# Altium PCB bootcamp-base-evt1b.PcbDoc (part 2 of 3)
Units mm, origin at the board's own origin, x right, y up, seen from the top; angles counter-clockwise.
Board outline 49.31 x 77.41 mm, 4 copper layers (Top Layer, Internal Plane 1, Internal Plane 2, Bottom Layer), stack 1.597 mm thick; 178 components, 122 nets, 1398 pads, 353 vias.
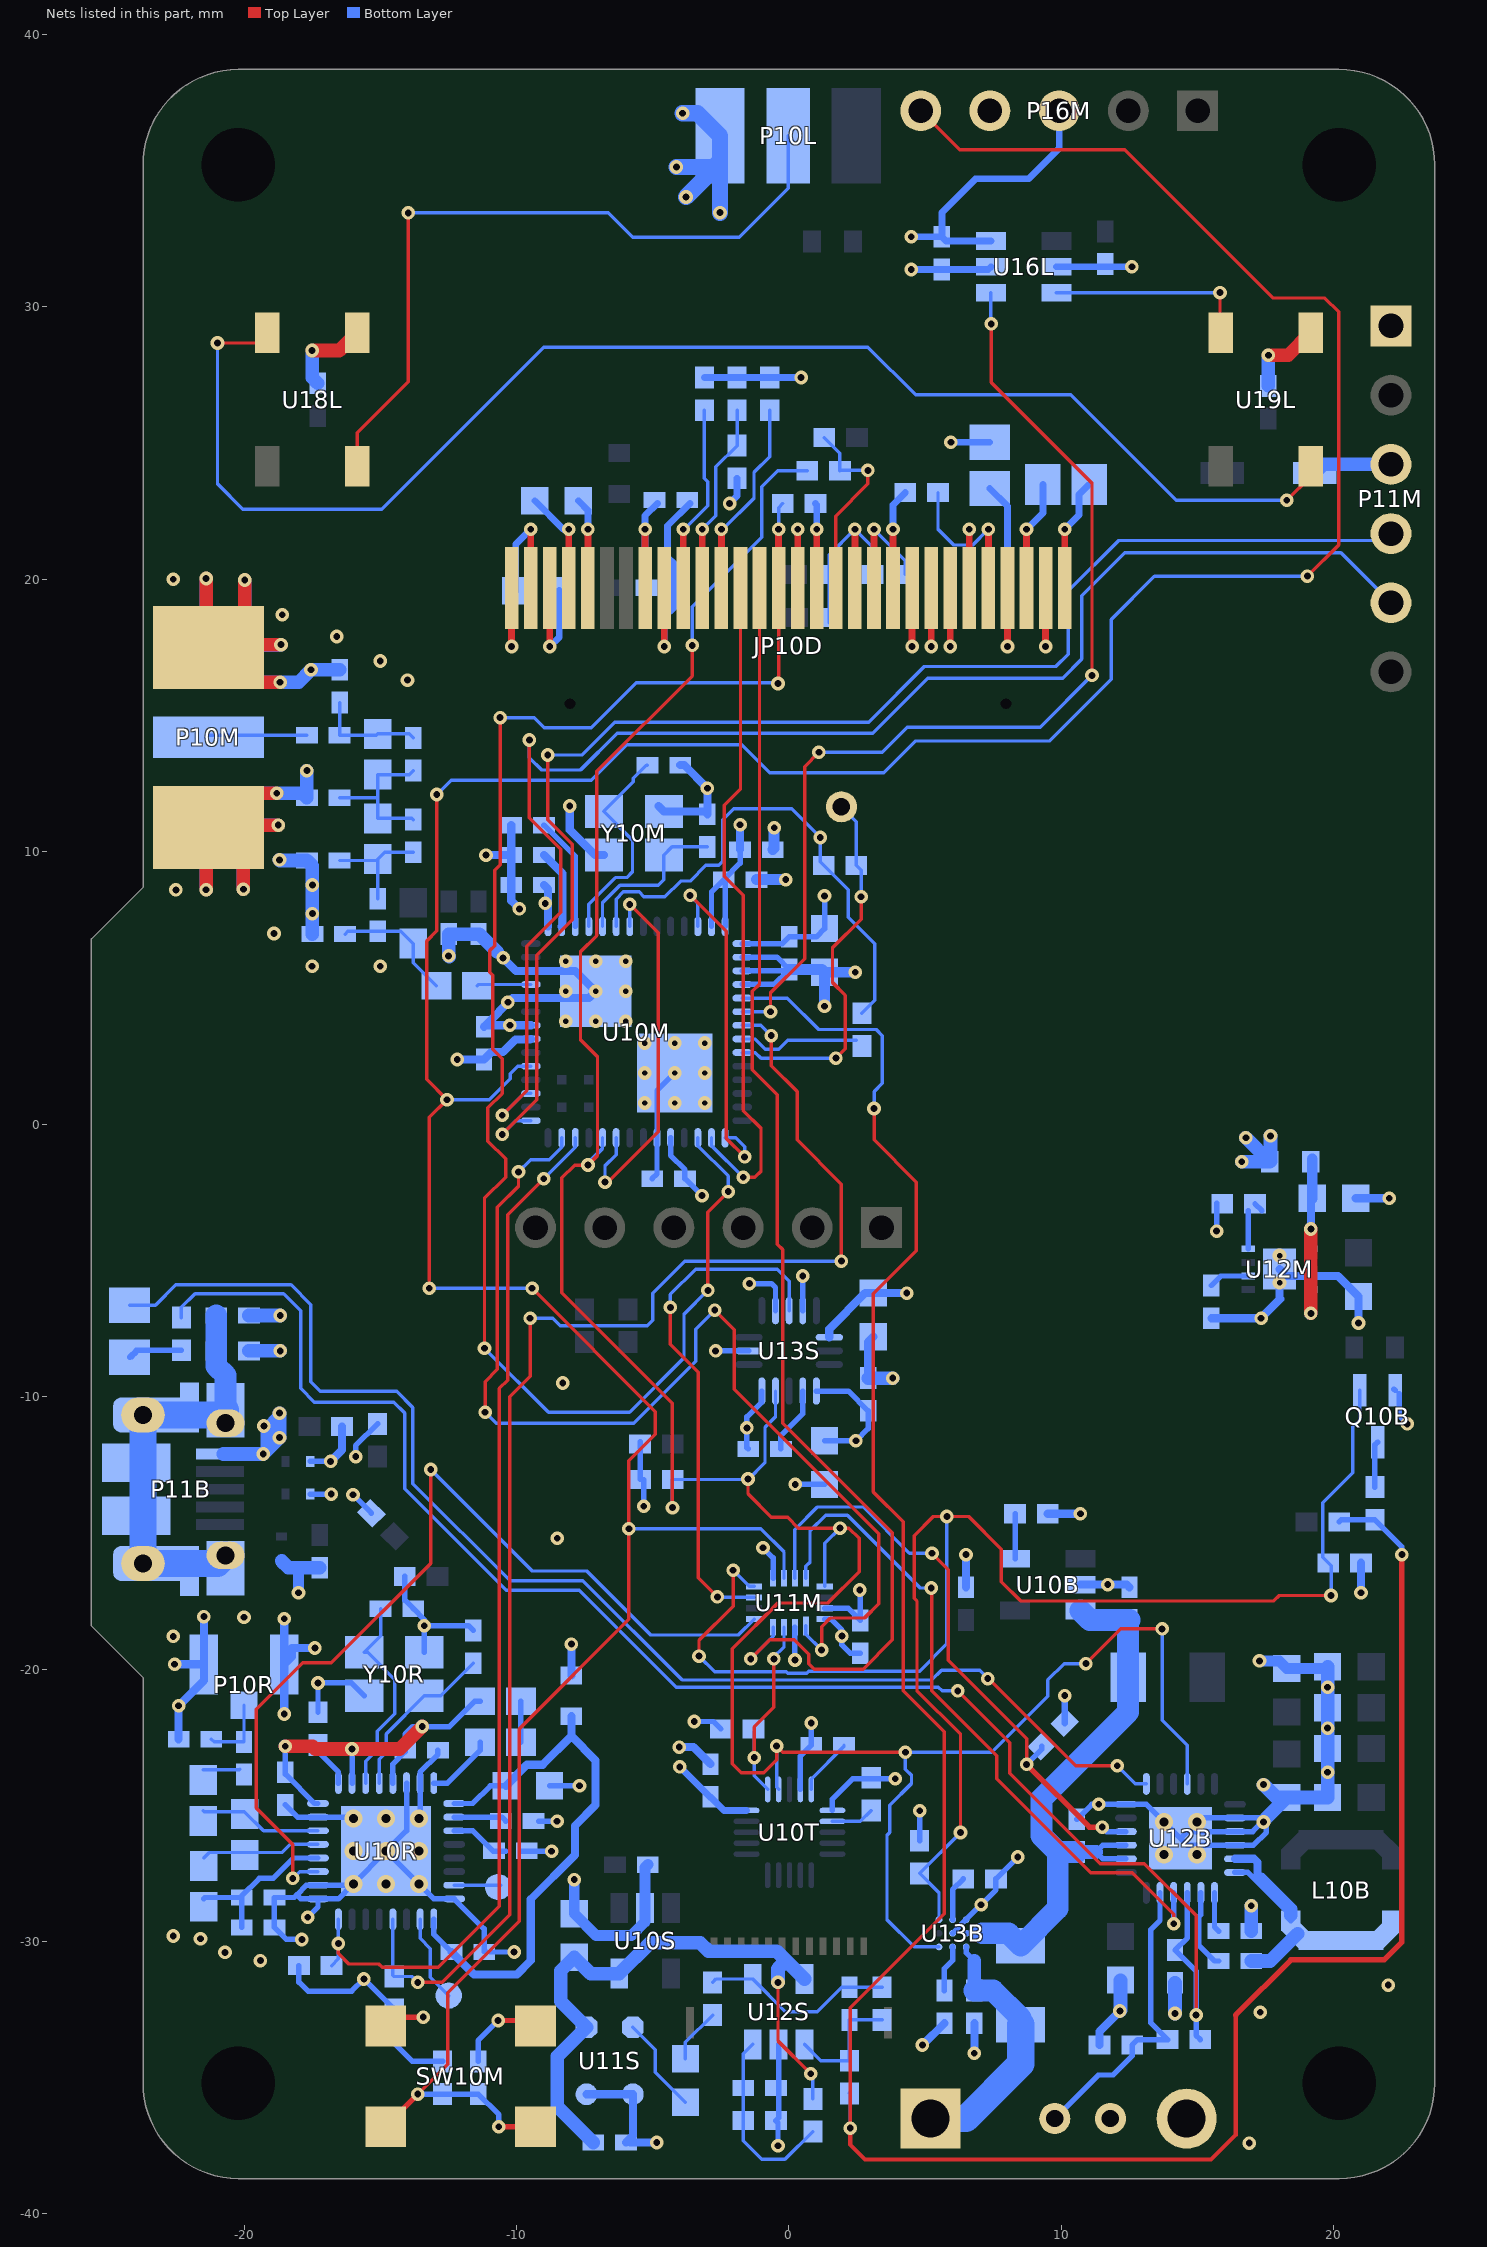
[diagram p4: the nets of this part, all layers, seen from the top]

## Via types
v1: diameter 0.5, hole 0.25, Top Layer to Bottom Layer, tented both sides, 320 vias
v2: diameter 0.5, hole 0.2, Top Layer to Bottom Layer, 18 vias
v3: diameter 0.66, hole 0.33, Top Layer to Bottom Layer, tented top, 13 vias
v4: diameter 0.5, hole 0.2, Top Layer to Bottom Layer, tented top, 2 vias

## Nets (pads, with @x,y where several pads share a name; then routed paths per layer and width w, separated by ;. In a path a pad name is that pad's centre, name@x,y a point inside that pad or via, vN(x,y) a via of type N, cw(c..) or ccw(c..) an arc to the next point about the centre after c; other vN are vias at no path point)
ACCEL_INT: U11M.7 U13S.11 | length 19.2
  Top Layer w0.125: v1(-4.35,-6.725) -4.35,-8.075 -3.325,-9.1 -3.325,-16.65 v1(-2.625,-17.35)
  Bottom Layer w0.125: v1(-4.35,-6.725) -4.35,-6.25 -3.425,-5.325 -0.425,-5.325 0.008,-5.758 U13S.11@0.008,-6.846 ; v1(-2.625,-17.35) -2.608,-17.367 U11M.7@-1.279,-17.367
BAT_CD: U11M.12 U12B.4 | length 25.6
  Top Layer w0.125: v1@5.25,-17.025 5.25,-20.8 7.625,-23.175 7.625,-24.025 11.075,-27.475 12.6,-27.475 14.125,-29 v1(14.125,-29.35)
  Bottom Layer w0.125: U11M.12@0.621,-16.667 0.621,-16.229 0.775,-16.075 0.775,-14.925 1.35,-14.35 2.15,-14.35 4.825,-17.025 v1(5.225,-17.025)
  Bottom Layer w0.2: U12B.4@14.122,-28.216 14.122,-29.347 v1(14.125,-29.35)
BAT_DRV: C23B.1 R17B.1 R18B.2 U12B.3 | length 60.8
  Top Layer w0.125: v1(6.2,-20.8) 8.1,-22.7 8.1,-23.825 11.425,-27.15 13.05,-27.15 14.947,-29.047 v1(14.947,-32.7)
  Bottom Layer w0.125: R17B.1@-22.3,-7.1 -22.3,-6.725 -21.8,-6.225 -18.55,-6.225 -17.925,-6.85 -17.925,-9.7 -17.425,-10.2 -14.5,-10.2 -14.1,-10.6 -14.1,-13.375 -10.375,-17.1 -7.7,-17.1 -4.139,-20.661 5.486,-20.661 5.625,-20.8 v1(6.2,-20.8)
  Bottom Layer w0.2: U12B.3@14.622,-28.216 14.622,-29.866 C23B.1@14.172,-30.316 14.947,-31.091 v1(14.947,-32.7) 14.947,-33.447 R18B.2@15.1,-33.6
BAT_INT: R19B.1 U11M.11 U12B.10 | length 22.6
  Top Layer w0.125: v1(5.25,-15.75) 5.85,-16.35 5.85,-19.675 8.725,-22.55 v1(8.725,-23.5)
  Top Layer w0.2: v1(8.725,-23.5) 11.025,-25.8 v1(11.5,-25.8)
  Bottom Layer w0.125: U11M.11@0.221,-16.667 0.221,-14.879 1.05,-14.05 2.725,-14.05 4.425,-15.75 v1(5.25,-15.75)
  Bottom Layer w0.2: v1(8.725,-23.5) 9.276,-22.949 R19B.1@9.276,-22.824 ; v1(11.5,-25.8) 11.666,-25.966 U12B.10@12.372,-25.966
BAT_PMID: C22B.1 U12B.1 | length 1.5
  Bottom Layer w0.2: U12B.1@15.622,-28.216 15.622,-29.466 C22B.1@15.772,-29.616
BAT_POS: C10B.1 C21B.1 R21B.1 R25B.1 U10B.3 U12B.8 U12B.9 U13B.C2 | length 22
  Bottom Layer w0.2: U13B.C2@6.508,-29.7 6.9,-29.7 ; U12B.8@12.372,-26.966 11.522,-26.966 11.272,-26.716 11.522,-26.466 U12B.9@12.372,-26.466
  Bottom Layer w0.4: 6.9,-29.7 7.1,-29.7
  Bottom Layer w0.5: C21B.1@10.572,-26.716 11.272,-26.716
  Bottom Layer w0.8: 7.1,-29.7 8.058,-29.7 R21B.1@8.508,-30.15 9.872,-28.787 9.872,-26.716 ; C21B.1@10.572,-26.716 9.872,-26.716 ; U10B.3@10.7,-17.85 11.05,-18.2 C10B.1@12.5,-18.2 12.45,-18.25 R25B.1@12.45,-20.3 12.45,-21.575 9.272,-24.753 9.272,-26.116 9.872,-26.716
BAT_RAW: C25B.1 J10B.1 R21B.2 U13B.C3 | length 9.7
  Bottom Layer w0.2: U13B.C3@6.508,-30.2 6.508,-30.408 6.8,-30.7
  Bottom Layer w0.5: 6.8,-30.7 6.808,-30.708 C25B.1@6.808,-31.8
  Bottom Layer w0.8: C25B.1@6.808,-31.8 7.5,-31.8 8.508,-32.808 R21B.2@8.508,-33.05
  Bottom Layer w1: J10B.1@5.2,-36.5 6.5,-36.5 8.508,-34.492 R21B.2@8.508,-33.05
BAT_STAT: D10B.2 U12B.13 | length 48.7
  Top Layer w0.125: v1@7.35,-20.375 10.525,-23.55 v1(12.05,-23.55)
  Bottom Layer w0.125: D10B.2@-24.2,-6.65 -23.25,-6.65 -22.5,-5.9 -18.275,-5.9 -17.55,-6.625 -17.55,-9.45 -17.2,-9.8 -14.4,-9.8 -13.8,-10.4 -13.8,-13.2 -10.236,-16.764 -7.561,-16.764 -3.925,-20.4 5.25,-20.4 5.6,-20.05 7,-20.05 v1(7.3,-20.35) ; v1(12.05,-23.55) 12.716,-24.216 U12B.13@13.122,-24.216
BAT_SW: C14B.2 L10B.1 U12B.23 U12B.24 | length 8.3
  Bottom Layer w0.2: U12B.24@16.372,-27.466 16.847,-27.466 18.422,-29.041 L10B.1@18.422,-29.241
  Bottom Layer w0.3: U12B.23@16.372,-26.966 17.072,-26.966 17.197,-27.091 17.197,-27.716
  Bottom Layer w0.5: C14B.2@16.972,-30.716 17.672,-30.716 L10B.1@18.672,-29.716 ; 17.322,-27.716 18.422,-28.816 L10B.1@18.422,-29.041
BAT_TS: J11B.1 R18B.1 R20B.2 U12B.5 | length 11.4
  Bottom Layer w0.2: J11B.1@9.76,-36.5 11.36,-34.9 11.9,-34.9 12.6,-34.2 R20B.2@12.6,-33.8 12.8,-33.6 R18B.1@13.9,-33.6 13.275,-32.975 13.275,-29.575 13.622,-29.228 U12B.5@13.622,-28.216
BLE_ANT: C14R.2 C15R.2 P10R.SIG | length 2.6
  Bottom Layer w0.125: C15R.2@-21.2,-22.575 -21.1,-22.675 C14R.2@-20,-22.675 P10R.SIG@-20,-21.325
BLE_ANT1: L13R.2 L14R.1 U10R.21 | length 4.4
  Bottom Layer w0.125: L14R.1@-21.486,-26.934 -21.286,-26.734 -19.986,-26.734 -18.611,-26.734 -18.311,-26.434 U10R.21@-17.286,-26.434
BLE_ANT2: L12R.1 L13R.1 U10R.22 | length 4.5
  Bottom Layer w0.125: L12R.1@-21.5,-25.2 -21.466,-25.234 -19.986,-25.234 -19.286,-25.934 U10R.22@-17.286,-25.934
BLE_AVDD: C12R.1 C13R.1 L10R.2 U10R.24 U10R.26 U10R.29 | length 14.6
  Top Layer w0.5: v1(-18.486,-22.834) -17.486,-22.834 -17.386,-22.934 v1(-16.036,-22.934) -14.286,-22.934 v1(-13.461,-22.109)
  Bottom Layer w0.2: v1(-18.486,-22.834) C13R.1@-18.486,-23.784 -18.486,-23.859 -17.411,-24.934 U10R.24@-17.286,-24.934 ; U10R.26@-16.036,-24.184 v1(-16.036,-22.934) ; U10R.29@-14.536,-24.184 -14.536,-23.484 -14.086,-23.034 C12R.1@-14.086,-22.984 -14.086,-22.384 -13.811,-22.109 v1(-13.461,-22.109) -12.461,-22.109 -11.536,-21.184 L10R.2@-11.336,-21.184
BLE_IREF: R10R.2 U10R.25 | length 1.7
  Bottom Layer w0.2: R10R.2@-17.286,-22.784 -17.286,-23.034 -16.536,-23.784 U10R.25@-16.536,-24.184
BLE_RDYN: R11R.1 U10M.26 U10R.16 | length 38.6
  Top Layer w0.125: v1(-16.536,-30.075) -16.536,-30.439 -16.15,-30.825 -15.05,-30.825 -14.925,-30.95 -12.875,-30.95 -10.625,-28.7 -10.625,-9.7 -10.325,-9.4 -10.325,-3.325 v1(-9,-2)
  Bottom Layer w0.125: R11R.1@-16.786,-30.884 -16.536,-30.634 v1(-16.536,-30.075) U10R.16@-16.536,-29.184 ; v1(-9,-2) -7.842,-0.842 U10M.26@-7.842,-0.501
BLE_REQN: R12R.1 U10M.7 U10R.12 | length 53.4
  Top Layer w0.125: v1(-13.625,-31.5) -12.725,-31.5 -10.25,-29.025 -10.25,-10 -9.5,-9.25 v1(-9.5,-7.125) ; v1(-0.65,3.25) -0.65,2.15 0.3,1.2 0.3,-0.575 1.925,-2.2 v1(1.925,-5.025)
  Bottom Layer w0.125: U10R.12@-14.536,-29.184 -14.536,-31.234 R12R.1@-14.486,-31.284 -13.841,-31.284 v1(-13.625,-31.5) ; v1(-9.5,-7.125) -8.675,-7.125 -8.4,-7.4 -5.2,-7.4 -5,-7.2 -5,-6.2 -3.825,-5.025 v1(1.925,-5.025) ; U10M.7@-1.712,3.629 -1.029,3.629 v1(-0.65,3.25)
BLE_RST: U10R.19 U11M.5 | length 34.5
  Top Layer w0.125: v1(-18.211,-27.684) -18.211,-26.439 -19.55,-25.1 -19.55,-21.475 -17.85,-19.775 -16.8,-19.775 -13.15,-16.125 v1(-13.15,-12.675)
  Bottom Layer w0.125: v1(-18.211,-27.684) -17.961,-27.434 U10R.19@-17.286,-27.434 ; v1(-13.15,-12.675) -9.425,-16.4 -7.425,-16.4 -5.075,-18.75 -1.862,-18.75 U11M.5@-1.279,-18.167
BLE_VDDPA: C19R.2 C20R.2 L14R.2 U10R.20 | length 6
  Bottom Layer w0.2: L14R.2@-21.486,-28.434 -21.436,-28.384 C19R.2@-20.086,-28.384 ; C20R.2@-20.086,-29.484 C19R.2@-20.086,-28.384 ; U10R.20@-17.286,-26.934 -18.186,-26.934 -18.936,-27.684 -19.436,-27.684 -20.086,-28.334 C19R.2@-20.086,-28.384
BLE_XC1: C10R.1 U10R.28 Y10R.2 | length 6.2
  Bottom Layer w0.125: U10R.28@-15.036,-24.184 -15.036,-23.309 -14.786,-23.059 -14.786,-22.384 Y10R.2@-13.386,-20.984 -12.786,-20.984 C10R.1@-11.586,-19.784
BLE_XC2: C11R.1 U10R.27 Y10R.1 | length 7.6
  Bottom Layer w0.125: U10R.27@-15.536,-24.184 -15.536,-23.384 -15.111,-22.959 -15.111,-22.284 -14.461,-21.634 -14.461,-20.384 -15.461,-19.384 Y10R.1@-15.586,-19.384 -14.986,-18.784 C11R.1@-14.986,-17.784
BS0: JP10D.10 R11D.2 | length 7
  Top Layer w0.25: JP10D.10@-3.878,19.684 v1(-3.878,21.834)
  Bottom Layer w0.125: v1(-3.878,21.834) -3.838,21.834 -2.978,22.694 -2.978,23.584 -3.103,23.709 R11D.2@-3.103,26.209
BS1: JP10D.11 R15D.2 R16D.2 | length 7.1
  Top Layer w0.25: JP10D.11@-3.178,19.684 v1(-3.178,21.834)
  Bottom Layer w0.125: v1(-3.178,21.834) -2.678,22.334 -2.678,24.134 R16D.2@-1.903,24.909 R15D.2@-1.903,26.209
BS2: JP10D.12 R17D.2 | length 7.3
  Top Layer w0.25: JP10D.12@-2.478,19.684 v1(-2.478,21.834)
  Bottom Layer w0.125: v1(-2.478,21.834) -2.428,21.834 -1.281,22.981 -1.281,23.922 -0.703,24.5 R17D.2@-0.703,26.209
DAC0_OUT: J17M.1 R15M.2 U10M.9 | length 13.8
  Top Layer w0.125: v1(1.725,2.425) 2.075,2.775 2.075,4.725 1.6,5.2 1.6,6.475 2.65,7.525 v1(2.65,8.35)
  Bottom Layer w0.125: U10M.9@-1.712,2.629 -1.229,2.629 -1.025,2.425 v1(1.725,2.425) ; J17M.1@1.925,11.65 2.475,11.1 R15M.2@2.475,9.5 2.65,9.325 v1(2.65,8.35) v1@2.675,8.35
DUART_RX: P11M.4 U10M.29 | length 52.3
  Top Layer w0.125: v1(-10.525,-0.375) -9.25,0.9 -9.25,6.2 -7.95,7.5 -7.95,10.275 -8.85,11.175 v1(-8.85,13.55)
  Bottom Layer w0.125: v1(-10.525,-0.375) -10.021,0.129 U10M.29@-9.472,0.129 ; v1(-8.85,13.55) -7.6,13.55 -6.4,14.75 2.925,14.75 4.975,16.8 9.8,16.8 10.25,17.25 10.25,19.575 12.1,21.425 21.825,21.425 22.08,21.68 P11M.4@22.1,21.68
DUART_TX: P11M.5 U10M.31 | length 54.4
  Top Layer w0.125: v1(-10.525,0.325) -9.625,1.225 -9.625,6.525 -8.375,7.775 -8.375,10.099 -9.525,11.249 v1(-9.525,14.1)
  Bottom Layer w0.125: v1(-10.525,0.325) -9.721,1.129 U10M.31@-9.472,1.129 ; v1(-9.525,14.1) -9.525,13.45 -9.075,13 -7.65,13 -6.3,14.35 3.075,14.35 5.1,16.375 10.05,16.375 10.75,17.075 10.75,19.4 12.325,20.975 20.265,20.975 P11M.5@22.1,19.14
GG_INT: Q10B.1 R22B.1 R28B.2 U11M.8 U13B.A1 | length 60.8
  Top Layer w0.125: v1(-3.3,-19.525) -3.3,-18.95 -2.05,-17.7 v1(-2.05,-16.375) ; v1(6.3,-26) 6.3,-22.4 4.7,-20.8 4.7,-17.5 4.6,-17.4 4.6,-15.1 5.3,-14.4 v1(5.8,-14.4) 6.6,-14.4 7.8,-15.6 7.8,-16.8 8.5,-17.5 17.8,-17.5 18,-17.3 v1(19.9,-17.3)
  Bottom Layer w0.125: v1(-3.3,-19.525) -2.725,-20.1 -0.1,-20.1 -0.05,-20.15 0.65,-20.15 0.725,-20.075 4.8,-20.075 5.8,-19.075 v1(5.8,-14.4) ; v1(-2.05,-16.375) -1.458,-16.967 U11M.8@-1.279,-16.967 ; U13B.A1@5.508,-29.2 5.508,-28.208 R22B.1@4.8,-27.5 v1(6.3,-26) ; v1(19.9,-17.3) 19.9,-16.2 R28B.2@19.8,-16.1 19.6,-15.9 19.6,-13.9 20.7,-12.8 20.7,-11.1 20.958,-10.842 Q10B.1@20.958,-9.771
GG_VDD: C26B.1 U13B.B3 | length 1.7
  Bottom Layer w0.2: C26B.1@5.708,-31.8 5.708,-30.992 6.008,-30.692 U13B.B3@6.008,-30.2
GND: C10B.2 C10L.2 C10M.2 C10R.2 C10S.2 C10T.2 C11B.2 C11L.2 C11M.2 C11R.2 C11S.2 C11T.2 C12D.2 C12L.2 C12M.2 C12R.2 C13D.2 C13L.2 C13M.2 C13R.2 C14D.2 C14M.2 C14S.2 C15B.2 C15D.2 C15M.2 C15R.1 C15S.2 C16B.2 C16M.2 C16R.2 C16S.2 C17B.2 C17M.2 C17R.2 C17S.2 C18B.2 C18M.2 C18R.1 C18S.2 C19B.2 C19M.2 C19R.1 C19S.2 C20B.2 C20M.2 C20R.1 C21B.2 C21R.2 C22B.2 C23B.2 C24B.2 C25B.2 C25M.2 C26B.2 C26M.1 C27B.2 C27M.2 C28B.2 C28M.2 C29M.2 C30M.2 C31M.2 C32M.2 C33M.2 C34M.2 C35M.1 D11B.2 D12B.2 D13B.2 J12B.1 J13B.1 JP10D.1 JP10D.8 JP10D.16 JP10D.17 JP10D.21 JP10D.22 JP10D.23 JP10D.24 JP10D.25 JP10D.29 JP10D.30 P10L.1 P10M.2 P10R.GND P11B.5 P11M.1 P16M.4 Q10B.2 R10R.1 R11D.1 R13S.1 R14D.2 R15D.1 R16B.2 R17D.1 R18D.2 R20B.1 R23B.1 R24B.2 R28B.1 R31B.2 R32B.2 R34T.1 SW10M.1 SW10M.2 U10B.2 U10M.2 U10M.3 U10M.4 U10M.20 U10M.36 U10M.38 U10M.40 U10M.61 U10M.62 U10R.8 U10R.17 U10R.18 U10R.23 U10R.30 U10R.31 U10R.33 U10S.2 U10T.4 U10T.6 U11M.9 U11M.16 U11S.2 U11S.3 U12B.12 U12B.20 U12B.21 U12B.22 U12B.25 U12M.3 U12M.9 U12S.2 U13B.B2 U13B.C1 U13S.5 U13S.7 U13S.10 U13S.12 U16L.2 U16L.5 U18L.3 U19L.3 Y10M.3 Y10M.4 Y10R.3 Y10R.4 | length 300.3
  Top Layer w0.2: SW10M.2@-14.8,-33.1 -14.475,-32.775 v1(-13.425,-32.775) ; v1(-10.675,-32.9) -9.5,-32.9 SW10M.1@-9.3,-33.1
  Top Layer w0.25: v1(-10.178,17.534) JP10D.1@-10.178,19.684 ; JP10D.8@-5.278,19.684 v1(-5.278,21.834) ; JP10D.16@0.322,19.684 v1(0.322,21.834) ; JP10D.17@1.022,19.684 v1(1.022,21.834) ; JP10D.21@3.822,19.684 v1(3.822,21.834) ; v1(4.522,17.534) JP10D.22@4.522,19.684 ; v1(5.222,17.534) JP10D.23@5.222,19.684 ; v1(5.922,17.534) JP10D.24@5.922,19.684 ; JP10D.25@6.622,19.684 v1(6.622,21.834) ; v1(9.422,17.534) JP10D.29@9.422,19.684 ; JP10D.30@10.122,19.684 v1(10.122,21.834)
  Top Layer w0.5: v1(-21.392,8.604) -21.392,10.814 P10M.2@-21.307,10.898 ; v1(-21.392,20.029) -21.392,17.586 P10M.2@-21.307,17.502 ; v1(-20.025,8.625) -20.025,9.616 P10M.2@-21.307,10.898 ; v1(-19.975,19.975) -19.975,18.834 P10M.2@-21.205,17.604 ; v1(-18.8,12.15) -20.055,12.15 P10M.2@-21.226,10.979 ; v1(-18.742,10.979) P10M.2@-21.226,10.979 ; v1(-18.675,16.225) -20.03,16.225 P10M.2@-21.307,17.502 ; v1(-18.642,17.604) P10M.2@-21.205,17.604 ; v1(-17.5,28.4) -16.5,28.4 U18L.3@-15.85,29.05 ; v1(17.6,28.225) 18.325,28.225 U19L.3@19.15,29.05 ; P10M.2@-21.307,10.898 P10M.2@-21.226,10.979 ; P10M.2@-21.307,17.502 P10M.2@-21.205,17.604
  Bottom Layer w0.2: C13R.2@-18.486,-24.984 -18.036,-25.434 U10R.23@-17.286,-25.434 -16.036,-25.434 v3(-15.986,-25.484) ; v1(-17.875,-29.925) -18.445,-29.925 C20R.1@-18.886,-29.484 C19R.1@-18.886,-28.384 -18.161,-28.384 -18.061,-28.284 ; v1(-17.661,-29.109) -17.286,-28.734 U10R.17@-17.286,-28.434 ; D12B.2@-17.573,-13.579 v1(-16.798,-13.579) ; D13B.2@-17.573,-12.379 v1(-16.823,-12.379) ; R10R.1@-17.286,-21.584 v1(-17.286,-20.509) -16.061,-20.509 Y10R.4@-15.586,-20.984 ; R31B.2@-14.1,-16.6 -14.1,-17.47 C11R.2@-13.786,-17.784 -13.386,-18.184 v1(-13.386,-18.409) ; U10R.30@-14.036,-24.184 -14.036,-25.934 v3(-14.786,-26.684) ; v3(-13.586,-25.484) -13.536,-25.434 U10R.31@-13.536,-24.184 -13.536,-23.784 -12.886,-23.134 C12R.2@-12.886,-22.984 ; Y10R.3@-13.386,-19.384 v1(-13.386,-18.409) ; C10R.2@-11.586,-18.584 -11.761,-18.409 v1(-13.386,-18.409) ; C31M.2@-11.408,-34.4 -11.408,-33.633 v1(-10.675,-32.9) ; v1(-10.086,-30.384) C21R.2@-11.186,-30.384 -11.186,-29.534 U10R.8@-12.286,-28.434 -13.036,-28.434 v3(-13.586,-27.884) v3(-14.786,-26.684) ; C18R.1@-9.811,-26.684 v1(-8.711,-26.684) ; C17R.2@-9.186,-25.584 v1(-8.509,-25.584) ; C16R.2@-8.786,-24.284 v1(-7.686,-24.284) ; C30M.2@-5.017,-1.996 -4.842,-1.821 U10M.20@-4.842,-0.501 -4.842,1.229 v2(-4.192,1.879) ; v1(-2.692,-8.321) U13S.7@-1.467,-8.321 ; U10M.4@-1.712,5.129 -0.542,5.129 C12M.2@-0.042,5.629 ; U10M.3@-1.712,5.629 C12M.2@-0.042,5.629 ; U10M.2@-1.712,6.129 -0.442,6.129 C12M.2@0.008,5.679 C12M.2@-0.042,5.629 ; C19S.2@-1.492,-11.921 -1.542,-11.871 -1.542,-10.746 -0.992,-10.196 U13S.5@-0.992,-9.796 ; v1(-1.45,-5.85) -0.642,-5.85 -0.492,-6 U13S.10@-0.492,-6.846 ; v1(-0.95,-15.55) -0.579,-15.921 U11M.9@-0.579,-16.667 ; v1(-0.4,-37.5) -0.4,-36.656 R13S.1@-0.479,-36.577 -0.379,-36.477 -0.379,-35.377 U12S.2@-0.379,-33.777 ; v1(0.233,-13.221) C16S.2@1.308,-13.221 ; U10T.4@0.422,-24.416 0.422,-23.191 C11T.2@0.822,-22.791 v1(0.822,-21.978) ; U13S.12@0.508,-6.846 v1(0.508,-5.571) ; U11M.16@1.321,-18.167 1.546,-18.167 1.946,-18.567 1.946,-19.117 2.246,-19.417 C32M.2@2.621,-19.417 ; U10T.6@1.597,-25.191 1.597,-24.778 2.35,-24.025 v1@3.75,-24.025 ; U13B.B2@6.008,-29.7 U13B.C1@6.508,-29.2 7.6,-28.108 R23B.1@7.6,-27.7 v1(8.4,-26.9) ; C21B.2@10.572,-25.516 11.122,-24.966 U12B.12@12.372,-24.966 13.122,-24.966 v3(13.772,-25.616) U12B.25@14.372,-26.216 ; v3(14.972,-25.616) 15.122,-25.466 U12B.20@16.372,-25.466 v1@17.522,-25.466 ; Q10B.2@22.208,-9.721 Q10B.2@22.258,-9.771 ; Q10B.2@22.4,-9.9 22.4,-10.7 v1(22.7,-11) ; -18.061,-28.284 -17.911,-28.434 U10R.17@-17.286,-28.434 ; -18.061,-28.284 -17.711,-27.934 U10R.18@-17.286,-27.934 U10R.33@-16.036,-27.934 ; U10R.17@-17.286,-28.434 -16.536,-28.434 U10R.33@-16.036,-27.934 ; U10R.33@-16.036,-27.934 v3(-15.986,-27.884) v3(-14.786,-26.684) ; U12B.25@14.372,-26.216 14.622,-26.466 U12B.22@16.372,-26.466 17.047,-26.466 17.522,-25.991 v1@17.522,-25.466 ; U12B.25@14.372,-26.216 14.622,-25.966 U12B.21@16.372,-25.966 17.022,-25.966 v1@17.522,-25.466
  Bottom Layer w0.25: C12D.2@-5.228,19.684 -5.278,19.734 v1(-5.278,21.834) -5.278,22.334 C13D.2@-4.828,22.784 ; R11D.1@-3.103,27.409 R15D.1@-1.903,27.409 R17D.1@-0.703,27.409 v1(0.447,27.409) ; R14D.2@0.972,22.784 1.022,22.734 v1(1.022,21.834) ; v1(3.822,21.834) 3.822,22.734 R18D.2@4.272,23.184 ; v1(4.491,31.372) C11L.2@5.616,31.372 7.316,31.372 U16L.5@7.416,31.472 ; v1(5.947,25.034) C14D.2@7.372,25.034 ; U16L.2@9.816,31.472 v1(12.591,31.472) ; v1(10.122,21.834) 10.647,22.359 10.647,23.109 C15D.2@11.022,23.484
  Bottom Layer w0.3: v1(-22.55,-19.825) P10R.GND@-21.475,-19.825 ; C15R.1@-22.4,-22.575 v1(-22.4,-21.35) -21.475,-20.425 P10R.GND@-21.475,-19.825 ; v1(-21.475,-18.075) P10R.GND@-21.475,-19.825 ; v1(-18.525,-21.65) P10R.GND@-18.525,-19.825 ; v1(-18.525,-18.15) P10R.GND@-18.525,-19.825 ; v1(-17.4,-19.225) -18.25,-19.225 -18.25,-19.55 P10R.GND@-18.525,-19.825 ; v1(-16.823,-12.379) -16.4,-11.956 R32B.2@-16.4,-11.1 ; C16M.2@-11.192,3.579 C16M.2@-11.142,3.629 ; v1(-11.117,9.879) C17M.2@-10.192,9.879 ; -10.717,6.329 -10.017,5.629 U10M.40@-9.472,5.629 -7.842,5.629 v2(-7.092,4.879) -7.342,4.629 U10M.38@-9.472,4.629 -10.142,4.629 C16M.2@-11.142,3.629 ; C18M.2@-10.192,10.979 C17M.2@-10.192,9.879 ; v1(-9.892,7.904) -10.192,8.204 C17M.2@-10.192,9.879 ; U10M.36@-9.472,3.629 C16M.2@-11.142,3.629 ; v1(-8.042,11.679) -8.042,10.804 -7.117,9.879 Y10M.4@-6.792,9.879 ; U11S.2@-7.429,-35.607 U11S.3@-5.729,-35.607 -5.729,-37.127 C14S.2@-5.979,-37.377 ; C14S.2@-5.823,-37.379 v1(-4.848,-37.379) ; Y10M.3@-4.792,11.679 Y10M.3@-4.592,11.479 -3.092,11.479 C14M.2@-2.992,11.379 v1(-2.992,12.329) -3.842,13.179 C15M.2@-3.992,13.179 ; v1(-4.028,-22.866) -3.503,-22.866 C10T.2@-2.878,-23.491 ; C17S.2@2.908,-9.321 2.908,-7.992 C18S.2@3.1,-7.8 ; v1(4.9,-33.8) 4.908,-33.8 C26B.2@5.708,-33 ; C11B.2@6.5,-17 v1(6.5,-15.8) ; v1(6.8,-34.1) 6.808,-34.092 C25B.2@6.808,-33 ; R16B.2@9.5,-14.3 v1(10.7,-14.3) ; U10B.2@10.7,-16.9 12.4,-16.9 C10B.2@12.5,-17 ; R20B.1@11.4,-33.8 11.4,-33.3 v1(12.15,-32.55) ; C35M.1@15.508,-7.121 v1(17.333,-7.121) 18.033,-6.421 18.008,-6.396 v4(18.008,-5.821) ; U12M.9@18.008,-5.321 18.258,-5.571 U12M.3@19.158,-5.571 20.158,-5.571 C33M.2@20.908,-6.321 v1(20.908,-7.296) ; C34M.2@20.808,-2.721 v1(22.033,-2.721) ; v1(21,-17.2) R28B.1@21,-16.1
  Bottom Layer w0.4: v1(-18,-17.2) -18,-16.279 ; v1(-7.879,-27.727) C11S.2@-7.879,-28.977 -7.079,-29.777 -5.779,-29.777 -5.279,-29.277 U10S.2@-5.279,-28.777 -5.279,-27.277 C10S.2@-5.179,-27.177 ; C10M.2@-1.192,8.979 v1(-0.117,8.979) ; C13M.2@-0.592,10.079 -0.542,10.129 v1(-0.542,10.879) ; C12M.2@0.008,5.679 1.208,5.679 C11M.2@1.308,5.579 ; v1(1.308,4.329) C11M.2@1.308,5.579 ; v1(2.433,5.579) C11M.2@1.308,5.579 ; v1(17.275,-19.7) 18,-19.7 C28B.2@18.275,-19.975 19.712,-19.975 C17B.2@19.772,-19.916
  Bottom Layer w0.5: v1(-21.392,8.604) -21.392,10.977 P10M.2@-21.228,10.977 ; v1(-21.392,20.029) -21.392,17.581 P10M.2@-21.228,17.581 ; P11B.5@-20.769,-12.107 -19.301,-12.107 v1(-19.298,-12.104) v1(-18.698,-11.504) v1@-18.698,-10.726 ; v1(-20.025,8.625) -20.025,9.616 P10M.2@-21.307,10.898 P10M.2@-21.228,10.977 ; v1(-19.975,19.975) -19.975,18.834 P10M.2@-21.228,17.581 ; R24B.2@-19.821,-8.323 v1(-18.671,-8.323) ; C27B.2@-19.821,-7.023 v1(-18.671,-7.023) ; v1@-19.148,-11.954 -19.148,-11.176 v1@-18.698,-10.726 ; v1(-18.742,10.979) v1(-18.742,10.979) P10M.2@-21.228,10.977 ; v1(-18.7,9.7) -18.679,9.679 C26M.1@-17.692,9.679 -17.492,9.479 C25M.2@-17.492,6.979 ; v1(-18.698,-10.604) v1@-18.698,-10.726 ; v1(-18.642,17.604) -18.665,17.581 P10M.2@-21.228,17.581 ; D11B.2@-18.623,-16.029 -18.373,-16.279 -18,-16.279 C24B.2@-17.223,-16.279 ; v1(-17.692,12.979) C27M.2@-17.692,11.979 -17.863,12.15 v1(-18.8,12.15) -20.055,12.15 P10M.2@-21.228,10.977 ; v1(-17.5,28.4) -17.5,27.4 C12L.2@-17.3,27.2 ; C28M.2@-16.492,16.679 v1(-17.542,16.679) -17.995,16.225 v1(-18.675,16.225) -20.03,16.225 P10M.2@-21.307,17.502 P10M.2@-21.228,17.581 ; v1@-12.467,6.154 v1(-12.492,6.179) C20M.2@-12.492,6.979 C19M.2@-11.392,6.979 -11.367,6.979 -10.717,6.329 ; C17S.2@2.908,-9.321 v1(3.808,-9.321) ; v1(12.15,-32.55) 12.172,-32.528 C16B.2@12.172,-31.416 ; v1(14.172,-32.641) C23B.2@14.172,-31.516 ; C22B.2@16.972,-29.616 v1(16.972,-28.691) ; v1(17.422,-24.241) 17.897,-24.716 C20B.2@18.272,-24.716 ; v1@17.522,-25.466 C20B.2@18.272,-24.716 ; C13L.2@17.6,27.1 v1(17.6,28.225) ; C17B.2@19.772,-19.916 v1(19.772,-20.666) C19B.2@19.772,-21.416 C18B.2@19.772,-22.916 v1(19.772,-23.791) C15B.2@19.772,-24.716 C20B.2@18.272,-24.716
  Bottom Layer w0.6: v1(-4.128,35.134) -2.853,35.134 -2.803,35.084 P10L.1@-2.528,35.359 ; v1(-3.903,37.109) -3.353,37.109 P10L.1@-2.528,36.284 P10L.1@-2.528,35.359 ; v1(-3.778,34.034) P10L.1@-2.528,35.284 ; v1(-2.528,33.459) P10L.1@-2.528,35.284 ; P10L.1@-2.528,35.284 P10L.1@-2.528,35.359
  other v1: 16.9,-37.4 17.3,-32.6 22,-31.6 -19.4,-30.7 -20.7,-30.4 -21.6,-29.9 -22.6,-29.8 7.054,-28.654 17.422,-25.616 11.372,-24.966 3.9,-24.025 19.772,-22.166 -22.6,-18.8 1.946,-18.792 -20,-18.1 11.7,-16.9 -8.5,-15.2 -1.542,-11.146 -19.273,-11.079 -8.3,-9.5 -10.242,3.629 -10.317,4.479 -17.5,5.8 -15,5.8 -10.492,6.104 -18.9,7 -17.492,7.729 -22.5,8.6 -17.492,8.779 -14,16.3 -15,17 -16.6,17.9 -18.6,18.7 -22.6,20
  other v2: -5.292,0.779 -4.192,0.779 -3.092,0.779 -5.292,1.879 -3.092,1.879 -5.292,2.979 -4.192,2.979 -3.092,2.979 -8.192,3.779 -7.092,3.779 -5.992,3.779 -8.192,4.879 -5.992,4.879 -8.192,5.979 -7.092,5.979 -5.992,5.979
  other v3: -14.786,-27.884 13.772,-26.816 14.972,-26.816 -15.986,-26.684 -13.586,-26.684 -14.786,-25.484
  other v4: 18.008,-4.821
GPIO_INT: U10M.27 U11M.1 | length 40.3
  Top Layer w0.125: v1(-11.15,-10.575) -11.15,-9.45 -10.7,-9 -10.7,-3.05 -9.925,-2.275 v1(-9.925,-1.75) ; v1(-2.725,-6.825) -2,-7.55 -2,-9.725 3.3,-15.025 3.3,-17.6 2.775,-18.125 1.525,-18.125 1.2,-18.45 v1(1.2,-19.3)
  Bottom Layer w0.125: v1(-11.15,-10.575) -10.75,-10.975 -5.7,-10.975 -3.425,-8.7 -3.425,-7.525 v1(-2.725,-6.825) ; v1(-9.925,-1.75) -9.475,-1.3 -8.8,-1.3 -8.342,-0.842 U10M.27@-8.342,-0.501 ; U11M.1@0.621,-18.417 0.621,-18.721 v1(1.2,-19.3)
LDO_CC: C35M.2 U12M.6 | length 1.5
  Bottom Layer w0.2: C35M.2@15.508,-5.921 15.858,-5.571 U12M.6@16.858,-5.571
LED0: U10M.6 U16L.4 | length 38.1
  Top Layer w0.125: v1(-0.675,4.125) -0.675,4.825 0.575,6.075 0.575,13.125 v1(1.1,13.65) ; v1(7.425,29.375) 7.425,27.225 11.125,23.525 v1(11.125,16.475)
  Bottom Layer w0.125: U10M.6@-1.712,4.129 -0.679,4.129 v1(-0.675,4.125) ; v1(1.1,13.65) 3.425,13.65 4.35,14.575 9.225,14.575 v1(11.125,16.475) ; U16L.4@7.416,30.522 7.416,29.384 v1(7.425,29.375)
LED0_HV: U16L.3 U19L.4 | length 7.5
  Top Layer w0.125: v1(15.825,30.525) 15.825,29.075 U19L.4@15.85,29.05
  Bottom Layer w0.125: U16L.3@9.816,30.522 15.822,30.522 v1(15.825,30.525)
LED1: U18L.4 U19L.2 | length 53.3
  Top Layer w0.125: v1(-20.975,28.675) -19.525,28.675 U18L.4@-19.15,29.05 ; v1(18.275,22.9) 19.15,23.775 U19L.2@19.15,24.15
  Bottom Layer w0.125: v1@-20.9,28.75 v1(-20.975,28.675) -20.975,23.5 -20.05,22.575 -14.95,22.575 -9,28.525 2.9,28.525 4.65,26.775 10.35,26.775 14.225,22.9 v1(18.275,22.9)
LED2: P10L.2 U18L.2 | length 27.1
  Top Layer w0.125: U18L.2@-15.85,24.15 -15.85,25.375 -13.975,27.25 v1(-13.975,33.45)
  Bottom Layer w0.125: v1(-13.975,33.45) -6.625,33.45 -5.725,32.55 -1.825,32.55 -0.028,34.347 P10L.2@-0.028,36.284
MCU_RESET: C31M.1 P16M.5 R12M.2 SW10M.3 SW10M.4 U10M.33 U11M.10 | length 140.8
  Top Layer w0.125: v1(-13.625,-35.6) -12.525,-34.5 -12.525,-31.875 -9.9,-29.25 -9.9,-22.2 -5.875,-18.175 v1(-5.875,-14.85) -5.875,-12.35 -4.9,-11.375 -4.9,-10.55 v1(-9.425,-6.025) ; -13.2,-5.725 -13.2,0.25 v1(-12.55,0.9) -13.3,1.65 -13.3,6.725 -12.925,7.1 v1(-12.925,12.1) ; P16M.5@4.84,37.2 6.265,35.775 12.325,35.775 17.775,30.325 19.675,30.325 20.175,29.825 20.175,21.261 v1(19.032,20.118)
  Top Layer w0.2: SW10M.4@-14.8,-36.8 -13.625,-35.625 v1(-13.625,-35.6) ; v1(-10.65,-36.8) SW10M.3@-9.3,-36.8
  Bottom Layer w0.125: v1(-13.2,-6.025) v1@-13.175,-6.05 ; v1@-13.125,-6.025 v1(-9.425,-6.025) ; v1(-12.925,12.1) -12.4,12.625 -7.25,12.625 -5.95,13.925 -1.725,13.925 -0.7,12.9 3.475,12.9 4.639,14.064 9.564,14.064 11.825,16.325 11.825,18.525 13.418,20.118 v1(19.032,20.118) ; v1(-12.55,0.9) -11,0.9 -10.225,1.675 -10.225,1.85 -9.946,2.129 U10M.33@-9.472,2.129 ; v1(-5.875,-14.85) -1.031,-14.85 -0.179,-15.703 U11M.10@-0.179,-16.667
  Bottom Layer w0.2: v1(-13.625,-35.6) R12M.2@-12.708,-35.6 C31M.1@-11.408,-35.6 -10.65,-36.358 v1(-10.65,-36.8)
MIC_OUT: R10S.1 R26B.1 R27B.2 U10M.5 | length 95.3
  Top Layer w0.125: v1(2.25,-36.85) 2.25,-32.425 5.7,-28.975 5.7,-22.3 4.2,-20.8 4.2,-14.6 3.1,-13.5 3.1,-6.225 4.675,-4.65 4.675,-2.125 3.125,-0.575 v1(3.125,0.575)
  Top Layer w0.15: v1(2.25,-36.85) 2.25,-37.45 2.8,-38 15.5,-38 16.4,-37.1 16.4,-32.7
  Top Layer w0.2: 16.4,-32.7 18.425,-30.675 21.85,-30.675 22.5,-30.025 v1(22.5,-15.8)
  Bottom Layer w0.125: U10M.5@-1.712,4.629 -0.054,4.629 1.1,3.475 3.2,3.475 3.425,3.25 3.425,1.5 3.125,1.2 v1(3.125,0.575) ; R10S.1@2.221,-35.577 2.25,-35.606 v1(2.25,-36.85)
  Bottom Layer w0.2: R26B.1@20.2,-14.6 20.279,-14.521 R27B.2@21.508,-14.521 22.5,-15.513 v1(22.5,-15.8) v1@22.479,-15.821
MPR_IRQ: R26T.1 U10T.1 U11M.3 | length 7.5
  Top Layer w0.125: v1(-1.275,-23.25) -1.275,-22.125 -0.55,-21.4 v1(-0.55,-19.625)
  Bottom Layer w0.125: R26T.1@-1.278,-22.291 -1.278,-23.916 U10T.1@-0.778,-24.416 ; v1@-0.587,-19.587 -0.179,-19.179 U11M.3@-0.179,-18.467
NetC11T_1: C11T.1 U10T.5 | length 2.1
  Bottom Layer w0.125: U10T.5@0.822,-24.416 0.822,-24.041 2.022,-22.841 C11T.1@2.022,-22.791
NetC12S_1: C12S.1 R10S.2 R11S.2 U12S.1 | length 4.6
  Bottom Layer w0.125: U12S.1@0.571,-33.777 1.171,-34.377 R10S.2@2.221,-34.377 C12S.1@2.221,-32.877 R11S.2@3.421,-32.877
NetC12S_2: C12S.2 R11S.1 R14S.1 U12S.4 | length 7.1
  Bottom Layer w0.125: R14S.1@-2.8,-31.5 -2.677,-31.377 U12S.4@-1.329,-31.377 -0.129,-32.577 1.046,-32.577 1.946,-31.677 C12S.2@2.221,-31.677 R11S.1@3.421,-31.677
NetC13S_1: C13S.1 U11S.4 | length 3.6
  Bottom Layer w0.125: U11S.4@-5.729,-33.147 -4.9,-33.976 -4.9,-34.8 C13S.1@-3.8,-35.9
NetC13S_2: C13S.2 R14S.2 | length 2
  Bottom Layer w0.125: C13S.2@-3.8,-34.3 -3.8,-33.7 R14S.2@-2.8,-32.7
NetC14B_1: C14B.1 U12B.2 | length 2.9
  Bottom Layer w0.2: U12B.2@15.122,-28.216 15.122,-29.016 15.047,-29.091 15.047,-30.141 15.622,-30.716 C14B.1@15.772,-30.716
NetC14R_1: C14R.1 L12R.2 | length 1.4
  Bottom Layer w0.125: L12R.2@-21.5,-23.7 -20.175,-23.7 C14R.1@-20.15,-23.675
NetC15S_1: C15S.1 R12S.1 R13S.2 U12S.3 | length 6.9
  Bottom Layer w0.125: U12S.3@-1.329,-33.777 -1.679,-34.127 R13S.2@-1.679,-36.577 -1.679,-37.321 -1,-38 -0.144,-38 R12S.1@0.877,-36.979
NetC17M_1: C17M.1 U10M.44 | length 2.9
  Bottom Layer w0.3: C17M.1@-8.992,9.879 -8.317,9.204 -8.317,7.284 U10M.44@-8.342,7.259
NetC17R_1: C17R.1 U10R.2 | length 2
  Bottom Layer w0.2: U10R.2@-12.286,-25.434 -10.536,-25.434 C17R.1@-10.386,-25.584
NetC18M_1: C18M.1 U10M.45 | length 4.2
  Bottom Layer w0.2: C18M.1@-8.992,10.979 -7.842,9.829 U10M.45@-7.842,7.259
NetC18R_2: C18R.2 U10R.3 | length 2.2
  Bottom Layer w0.2: U10R.3@-12.286,-25.934 -11.611,-25.934 -10.861,-26.684 -10.386,-26.684
NetC19S_1: C19S.1 U13S.2 | length 2.5
  Bottom Layer w0.2: C19S.1@-0.292,-11.921 -0.292,-11.421 0.508,-10.621 U13S.2@0.508,-9.796
NetC21M_1: C21M.1 C23M.2 C26M.2 L12M.1 | length 4.3
  Bottom Layer w0.125: C26M.2@-16.492,9.679 -15.142,9.679 L12M.1@-15.092,9.729 ; C23M.2@-15.092,8.279 L12M.1@-15.092,9.729 ; C21M.1@-13.792,9.979 -14.842,9.979 L12M.1@-15.092,9.729
NetC21M_2: C21M.2 C22M.1 C27M.1 L12M.2 L13M.1 | length 5.7
  Bottom Layer w0.125: C27M.1@-16.492,11.979 -15.142,11.979 -15.092,12.029 ; C21M.2@-13.792,11.179 -13.842,11.229 L12M.2@-15.092,11.229 -15.092,12.029 ; C22M.1@-13.792,12.979 -13.942,12.829 L13M.1@-15.092,12.829 -15.092,12.029
NetC22M_2: C22M.2 C24M.1 C28M.1 L13M.2 | length 4
  Bottom Layer w0.125: C28M.1@-16.492,15.479 C24M.1@-16.492,14.279 -15.142,14.279 L13M.2@-15.092,14.329 -13.942,14.329 C22M.2@-13.792,14.179
NetC23M_1: C23M.1 C25M.1 L10M.2 L11M.2 | length 4.6
  Bottom Layer w0.125: C25M.1@-16.292,6.979 -16.192,7.079 C23M.1@-15.092,7.079 -14.242,7.079 L10M.2@-13.792,6.629 -13.792,5.929 L11M.2@-12.942,5.079
NetC24M_2: C24M.2 P10M.1 | length 3.7
  Bottom Layer w0.125: P10M.1@-21.407,14.2 -21.328,14.279 C24M.2@-17.692,14.279
NetC27B_1: C27B.1 P11B.0 R24B.1 | length 15.8
  Bottom Layer w0.8: C27B.1@-21.021,-7.023 R24B.1@-21.021,-8.323 -21.021,-8.879 -20.677,-9.223 P11B.0@-20.677,-10.975
  Bottom Layer w1: P11B.0@-20.677,-15.825 -20.977,-16.125 P11B.0@-23.707,-16.125 P11B.0@-23.707,-10.675 P11B.0@-23.232,-10.675 -20.852,-10.675 P11B.0@-20.677,-10.5
NetD10B_1: D10B.1 R17B.2 | length 2.2
  Bottom Layer w0.2: D10B.1@-24.2,-8.55 -23.95,-8.3 R17B.2@-22.3,-8.3 ; D10B.1@-24.123,-8.529 D10B.1@-23.973,-8.379
NetD10M_1: D10M.1 P11M.3 | length 2.9
  Bottom Layer w0.5: D10M.1@19.3,23.9 19.62,24.22 P11M.3@22.1,24.22
NetJ10R_1: J10R.1 U10R.7 | length 1.7
  Bottom Layer w0.125: U10R.7@-12.286,-27.934 J10R.1@-10.575,-27.934
NetJ11R_1: J11R.1 U10R.10 | length 3.2
  Bottom Layer w0.125: U10R.10@-13.536,-29.184 -13.536,-29.884 -13.161,-30.259 -13.161,-31.309 J11R.1@-12.486,-31.984
NetJP10D_20: JP10D.20 R13D.1 | length 4.3
  Top Layer w0.25: JP10D.20@3.122,19.684 v1(3.122,21.834)
  Bottom Layer w0.125: v1(3.122,21.834) 4.272,20.684 R13D.1@4.272,20.184
NetL10R_1: L10R.1 L11R.2 | length 1.5
  Bottom Layer w0.2: L11R.2@-9.836,-22.684 L10R.1@-9.836,-21.184
NetL11R_1: L11R.1 U10R.32 | length 2.5
  Bottom Layer w0.2: U10R.32@-13.036,-24.184 -12.536,-24.184 -11.336,-22.984 L11R.1@-11.336,-22.684
NetQ10B_3: Q10B.3 R27B.1 | length 1.7
  Bottom Layer w0.2: R27B.1@21.508,-13.321 21.508,-11.771 Q10B.3@21.608,-11.671
NetR13M_2: R13M.2 U12M.8 | length 1.8
  Bottom Layer w0.2: U12M.8@16.858,-4.571 R13M.2@16.858,-3.171 ; R13M.2@17.108,-2.921 R13M.2@17.358,-3.171
NetR16B_1: R16B.1 U10B.5 | length 1.6
  Bottom Layer w0.2: U10B.5@8.3,-15.95 R16B.1@8.3,-14.3
NetR23B_2: R23B.2 U13B.B1 | length 1.7
  Bottom Layer w0.2: U13B.B1@6.008,-29.2 6.008,-28.092 R23B.2@6.4,-27.7
NetR34T_2: R34T.2 U10T.7 | length 1.6
  Bottom Layer w0.125: U10T.7@1.597,-25.591 2.622,-25.591 R34T.2@3.022,-25.191
OLED_C1N: C11D.1 JP10D.5 | length 3.3
  Top Layer w0.25: JP10D.5@-7.378,19.684 v1(-7.378,21.834)
  Bottom Layer w0.25: C11D.1@-7.728,22.884 -7.378,22.534 v1(-7.378,21.834)
OLED_C1P: C11D.2 JP10D.4 | length 3.8
  Top Layer w0.25: JP10D.4@-8.078,19.684 v1(-8.078,21.834)
  Bottom Layer w0.25: C11D.2@-9.328,22.884 -8.278,21.834 v1(-8.078,21.834)
OLED_C2N: C10D.1 JP10D.3 | length 4.3
  Top Layer w0.25: v1(-8.778,17.534) JP10D.3@-8.778,19.684
  Bottom Layer w0.25: v1(-8.778,17.534) -8.428,17.884 C10D.1@-8.428,19.584
OLED_C2P: C10D.2 JP10D.2 | length 4.6
  Top Layer w0.25: JP10D.2@-9.478,19.684 v1(-9.478,21.834)
  Bottom Layer w0.25: C10D.2@-10.028,19.584 -10.028,21.284 v1(-9.478,21.834)
OLED_CS: JP10D.13 U10M.16 | length 24.9
  Top Layer w0.125: JP10D.13@-1.778,19.684 -1.778,12.297 -2.375,11.7 -2.375,9.1 -1.675,8.4 -1.675,0.5 -1.025,-0.15 -1.025,-1.725 -1.25,-1.95 v1(-1.675,-1.95)
  Bottom Layer w0.125: U10M.16@-2.842,-0.501 -2.842,-0.783 v1(-1.675,-1.95)
OLED_D0: JP10D.18 R10D.1 R19D.1 | length 7.3
  Top Layer w0.125: JP10D.18@1.722,19.684 1.722,22.322 2.9,23.5 v1(2.9,24)
  Bottom Layer w0.125: R19D.1@1.3,25.2 1.872,24.628 R10D.1@1.872,23.984 1.887,24 v1(2.9,24)
OLED_D1: JP10D.19 R12D.1 R13D.2 R20D.1 | length 7.9
  Top Layer w0.25: JP10D.19@2.422,19.684 v1(2.422,21.834)
  Bottom Layer w0.125: R20D.1@1.472,18.397 R12D.1@1.472,20.184 1.472,20.884 v1(2.422,21.834) 3.072,21.184 R13D.2@3.072,20.184
OLED_DC: JP10D.15 R14D.1 U10M.17 | length 60.4
  Top Layer w0.125: v1(-11.175,-8.225) -11.175,-2.725 -10.4,-1.95 -10.4,-1.275 -11.05,-0.625 -11.05,0.6 -10.525,1.125 -10.525,2.4 -10.875,2.75 -10.875,5.475 -10.975,5.575 -10.975,6.375 -10.8,6.55 -10.8,9.325 -10.6,9.525 v1(-10.6,14.925) v1@-10.575,14.95 ; v1(-2.975,-6.1) -2.975,-3.225 v1(-2.225,-2.475) ; v1(-0.4,16.175) -0.378,16.197 JP10D.15@-0.378,19.684
  Top Layer w0.25: JP10D.15@-0.378,19.684 v1(-0.378,21.834)
  Bottom Layer w0.125: v1(-11.175,-8.225) -8.825,-10.575 -5.85,-10.575 -3.85,-8.575 -3.85,-6.975 v1(-2.975,-6.1) ; v1(-10.6,14.925) -9.35,14.925 -8.975,14.55 -7.25,14.55 -5.6,16.2 -0.425,16.2 v1(-0.4,16.175) ; U10M.17@-3.342,-0.501 -3.342,-0.783 -2.225,-1.9 v1(-2.225,-2.475) ; v1(-0.378,21.834) -0.378,22.634 R14D.1@-0.228,22.784
OLED_IREF: JP10D.26 R18D.1 | length 5.8
  Top Layer w0.25: JP10D.26@7.322,19.684 v1(7.322,21.834)
  Bottom Layer w0.125: R18D.1@5.472,23.184 5.472,21.834 6.047,21.259 6.747,21.259 v1(7.322,21.834)
OLED_RES: JP10D.14 U11M.4 | length 48.9
  Top Layer w0.125: v1(-1.4,-19.625) -0.7,-18.925 0.2,-18.925 0.725,-19.45 0.725,-19.8 0.925,-20 2.725,-20 3.8,-18.925 3.8,-15 -0.225,-10.975 -0.225,-4.6 -0.425,-4.4 -0.425,1.075 -1.35,2 -1.35,4.875 -1.078,5.147 JP10D.14@-1.078,19.684
  Bottom Layer w0.125: v1(-1.4,-19.625) -0.579,-18.804 U11M.4@-0.579,-18.467
OLED_VCC: C15D.1 JP10D.28 | length 4
  Top Layer w0.25: JP10D.28@8.722,19.684 v1(8.722,21.834)
  Bottom Layer w0.25: v1(8.722,21.834) 9.322,22.434 C15D.1@9.322,23.484
OLED_VCOMH: C14D.1 JP10D.27 | length 8.2
  Top Layer w0.25: v1(8.022,17.534) JP10D.27@8.022,19.684
  Bottom Layer w0.25: C14D.1@7.372,23.334 8.022,22.684 v1(8.022,17.534)
P3.0V: C10M.1 C10T.1 C11L.1 C11M.1 C12M.1 C13D.1 C13M.1 C16M.1 C16R.1 C16S.1 C17S.1 C18S.1 C21R.1 C29M.1 C30M.1 C32M.1 C34M.1 J12R.1 J16M.1 JP10D.9 P16M.3 R10M.2 R11M.2 R11R.2 R12M.1 R12R.2 R13M.1 R16D.1 R19B.2 R22B.2 R26T.2 R29B.2 R30B.2 U10M.1 U10M.19 U10M.35 U10M.43 U10M.55 U10M.56 U10R.1 U10R.9 U10T.20 U11M.2 U11M.15 U12M.1 U12M.4 U13S.1 U13S.14 U16L.6 | length 102
  Top Layer w0.25: v1(-4.578,17.534) JP10D.9@-4.578,19.684
  Top Layer w0.5: v1(19.158,-6.946) v1(19.158,-3.846)
  Bottom Layer w0.2: R11R.2@-17.986,-30.884 -17.986,-31.489 -17.65,-31.825 -16.05,-31.825 v1(-15.6,-31.375) -14.491,-32.484 -14.491,-33.734 -13.825,-34.4 R12M.1@-12.708,-34.4 ; v1(-16,-13.6) R30B.2@-15.324,-14.276 ; v1(-15.9,-12.2) -15.9,-11.8 R29B.2@-15.1,-11 ; U10R.9@-13.036,-29.184 -13.036,-29.734 C21R.1@-12.386,-30.384 ; U10R.1@-12.286,-24.934 -11.609,-24.934 -10.959,-24.284 C16R.1@-10.386,-24.284 ; R11M.2@-5.467,-11.658 -5.463,-11.662 R10M.2@-5.463,-13.041 ; v1(-5.325,-14.025) R10M.2@-5.325,-13.05 ; U10M.19@-4.342,-0.501 -4.342,-1.146 -3.817,-1.671 C30M.1@-3.817,-1.996 v1(-3.192,-2.621) v1@-3.142,-2.621 ; v1(-3.475,-21.925) -2.775,-21.925 R26T.2@-2.5,-22.2 ; U10M.55@-2.842,7.259 -2.842,8.529 C10M.1@-2.392,8.979 ; U10M.56@-2.342,7.259 -2.342,8.929 C10M.1@-2.392,8.979 ; v1@-1.8,11 v1(-1.792,10.992) ; C13M.1@-1.792,10.079 -1.792,9.579 C10M.1@-2.392,8.979 ; U10M.1@-1.712,6.629 -0.242,6.629 C12M.1@0.008,6.879 1.008,6.879 C11M.1@1.308,7.179 v1(1.308,8.379) ; v1(0.221,-19.667) U11M.2@0.221,-18.467 ; U13S.1@1.008,-9.796 2.183,-9.796 C17S.1@2.908,-10.521 2.908,-11.171 v1(2.458,-11.621) C16S.1@1.308,-11.621 ; U11M.15@1.321,-17.767 2.171,-17.767 C32M.1@2.621,-18.217 2.621,-17.321 2.6,-17.3 v1(2.6,-17.1) ; R22B.2@4.8,-26.3 v1(4.8,-25.2) ; v1(15.7,-3.925) R13M.1@15.7,-2.9 ; v1(19.158,-6.946) U12M.4@19.158,-6.071 ; C34M.1@19.158,-2.771 C34M.1@19.208,-2.721
  Bottom Layer w0.25: v1(-4.578,17.534) -4.578,18.609 -4.203,18.984 -4.203,20.559 -4.453,20.809 -4.453,21.967 -3.636,22.784 C13D.1@-3.628,22.784 ; v1(-4.003,-23.591) -2.903,-24.691 C10T.1@-2.878,-24.691 -2.378,-25.191 U10T.20@-1.553,-25.191 ; v1(-2.178,22.784) -1.903,23.059 R16D.1@-1.903,23.709 ; v1(4.491,32.572) C11L.1@5.616,32.572 ; U16L.6@7.416,32.422 5.766,32.422 C11L.1@5.616,32.572 ; P16M.3@9.92,37.2 9.92,35.82 8.8,34.7 6.85,34.7 5.616,33.466 C11L.1@5.616,32.572 ; R19B.2@10.124,-21.976 v1(10.125,-20.975)
  Bottom Layer w0.3: C21R.1@-12.386,-30.384 -11.561,-31.209 -9.986,-31.209 -9.475,-30.699 -9.475,-28.45 -7.85,-26.825 -7.85,-25.75 -7.095,-24.995 -7.095,-23.35 -7.986,-22.459 ; v1(-12.175,2.375) -12.171,2.379 C16M.1@-11.192,2.379 -10.917,2.654 -10.492,2.654 -10.042,3.104 -9.497,3.104 U10M.35@-9.472,3.129 ; C16R.1@-10.386,-24.284 -9.611,-23.509 -9.036,-23.509 -7.986,-22.459 ; C29M.1@-8.992,8.779 -8.842,8.629 U10M.43@-8.842,7.259 ; J12R.1@-7.986,-21.734 -7.986,-22.459 ; J12R.1@-7.986,-20.234 v1(-7.986,-19.084) ; C13M.1@-1.792,10.079 v1(-1.792,10.992) ; U13S.14@1.483,-7.821 1.483,-7.517 2.8,-6.2 C18S.1@3.1,-6.2 v1(4.325,-6.2) ; U12M.1@19.158,-4.571 C34M.1@19.158,-2.771
  Bottom Layer w0.4: C34M.1@19.208,-2.721 J16M.1@19.208,-1.271
  Bottom Layer w0.5: v1(16.625,-1.379) J16M.1@17.65,-1.379 ; v1(16.775,-0.5) 17.65,-1.375 J16M.1@17.65,-1.379 ; v1(17.675,-0.429) 17.675,-1.354 J16M.1@17.65,-1.379
  other v1: -8.942,8.104
P3.0V_MIC: C11S.1 C14S.1 R12S.2 U10S.5 U11S.1 U12S.5 | length 23.7
  Top Layer w0.125: v1(-0.4,-31.5) -0.4,-33.651 v1(0.8,-34.851)
  Bottom Layer w0.125: R12S.2@0.877,-35.779 v1@0.877,-34.929
  Bottom Layer w0.5: C14S.1@-7.179,-37.377 -8.5,-36.056 -8.5,-34.219 U11S.1@-7.429,-33.147 -8.379,-32.197 -8.379,-31.077 C11S.1@-7.879,-30.577 -7.279,-31.177 U10S.5@-6.229,-31.177 -5.104,-30.052 -3.254,-30.052 -2.954,-30.352 -0.454,-30.352 -0.106,-30.7 ; v1(-0.4,-31.5) -0.4,-30.994 -0.106,-30.7 ; U12S.5@0.571,-31.377 -0.106,-30.7
RF_CLK: U10M.15 U10M.54 | length 12.9
  Top Layer w0.125: v1(-3.625,8.4) -2.3,7.075 -2.3,-0.525 v1(-1.625,-1.2)
  Bottom Layer w0.125: v1(-3.625,8.4) -3.342,8.117 U10M.54@-3.342,7.259 ; U10M.15@-2.342,-0.501 -1.949,-0.501 -1.625,-0.825 v1(-1.625,-1.2)
RF_PKT_RDY: U10M.23 U10M.49 | length 14.1
  Top Layer w0.125: v1(-6.75,-2.125) -6.65,-2.125 -4.8,-0.275 -4.8,7.025 v1(-5.842,8.067)
  Bottom Layer w0.125: v1(-6.75,-2.125) -6.75,-1.525 -6.342,-1.117 U10M.23@-6.342,-0.501 ; v1@-5.85,8.075 v1(-5.842,8.067) U10M.49@-5.842,7.259
RF_RESET: R14M.1 R15M.1 U10M.48 | length 18.8
  Bottom Layer w0.125: U10M.48@-6.342,7.259 -6.342,8.258 -6.075,8.525 -5.5,8.525 -5.325,8.35 -4.55,8.35 -3.975,8.925 -3.625,8.925 -3.05,9.5 -2.575,9.5 -2.425,9.65 -2.425,11.175 -2.025,11.575 0.1,11.575 v1(1.15,10.525) 1.15,9.625 R15M.1@1.275,9.5 2.175,8.6 2.175,7.6 3.15,6.625 3.15,4.55 R14M.1@2.675,4.075
RF_RESET_PRE: R14M.2 U10M.8 | length 4.5
  Bottom Layer w0.125: U10M.8@-1.712,3.129 -1.254,3.129 -0.875,2.75 -0.375,2.75 -0.05,3.075 R14M.2@2.475,3.075
RF_XTA: C15M.1 U10M.46 Y10M.1 | length 7.9
  Bottom Layer w0.125: U10M.46@-7.342,7.259 -7.342,8.079 -6.367,9.054 -5.946,9.054 -5.742,9.258 -5.742,10.429 Y10M.1@-6.792,11.479 -5.707,12.563 -5.707,12.7 -5.228,13.179 C15M.1@-5.192,13.179
RF_XTB: C14M.1 U10M.47 Y10M.2 | length 6.1
  Bottom Layer w0.125: U10M.47@-6.842,7.259 -6.842,8.133 -6.2,8.775 -4.795,8.775 -4.592,8.979 Y10M.2@-4.592,9.879 -4.292,10.179 C14M.1@-2.992,10.179
RFIO: L11M.1 U10M.39 | length 2
  Bottom Layer w0.125: L11M.1@-11.442,5.079 -11.392,5.129 U10M.39@-9.472,5.129
SCL: R10D.2 R10M.1 U10M.24 U10T.2 U11M.13 U12B.16 U13B.A3 U13S.4 | length 108.1
  Top Layer w0.125: v1@-4.25,-14.1 v1(-4.275,-14.075) -4.275,-10.25 -8.338,-6.187 -8.338,-1.969 -7.869,-1.5 v1(-7.375,-1.5) -7.025,-1.15 -7.025,2.475 -7.65,3.1 -7.65,6.325 -7.05,6.925 -7.05,12.95 -3.55,16.45 v1(-3.55,17.575) ; v1(-1.5,-13.025) -1.5,-13.575 -0.65,-14.425 -0.05,-14.425 0.35,-14.825 v1(1.875,-14.825) 2.2,-14.825 2.575,-15.2 2.575,-16.425 1.425,-17.575 -0.4,-17.575 -2.075,-19.25 -2.075,-23.475 -1.75,-23.8 -0.925,-23.8 -0.45,-23.325 v1(-0.45,-22.825) -0.225,-23.05 v1(4.275,-23.05) ; v1(10.9,-19.8) 12.175,-18.525 v1(13.7,-18.525)
  Bottom Layer w0.125: v1(-7.375,-1.5) -7.375,-1.425 -6.842,-0.892 U10M.24@-6.842,-0.501 ; v1(-4.275,-14.075) -4.275,-13.054 R10M.1@-4.263,-13.041 -1.487,-13.041 -0.879,-12.434 -0.879,-11.134 -0.492,-10.746 U13S.4@-0.492,-9.796 ; v1(-3.55,17.575) -3.55,19 -1,21.55 -1,23.4 -0.416,23.984 R10D.2@0.672,23.984 ; v1(-0.45,-22.825) -0.45,-24.344 U10T.2@-0.378,-24.416 ; U11M.13@1.321,-16.967 1.321,-15.379 v1(1.875,-14.825) ; U13B.A3@5.508,-30.2 4.6,-30.2 3.6,-29.2 3.6,-26.1 3.7,-26 3.7,-25 4.5,-24.2 4.5,-23.9 4.275,-23.675 v1(4.275,-23.05) 7.45,-23.05 9.5,-21 9.5,-20.4 10.1,-19.8 v1(10.9,-19.8) ; v1(13.7,-18.525) 13.7,-21.875 14.622,-22.797 U12B.16@14.622,-24.216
